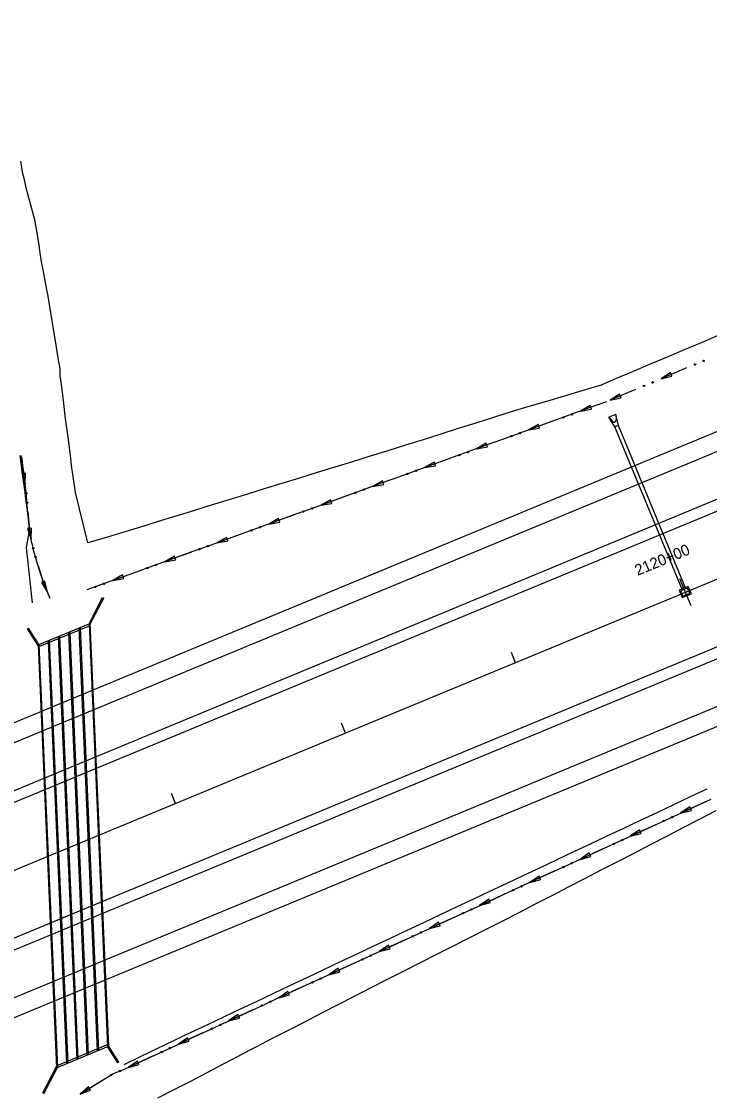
# Model space of a CAD drawing. Extents: x 1611108 to 1749517, y 619561 to 797725.
# Drawn here: x 1717725 to 1718099, y 766360 to 766944 of the extents above; entities that cross this region are included whole.
import ezdxf

# ---------------------------------------------------------------- set-up
doc = ezdxf.new("R2010")
doc.units = 0
for name, color, linetype in [('R_Ditch', 7, 'Continuous'), ('R_Drainage', 7, 'Continuous'), ('R_Horz Alg', 7, 'Continuous'), ('R_Horz Alg Stationing', 7, 'Continuous'), ('R_Proposed Const Limits', 7, 'Continuous'), ('R_Proposed Road', 7, 'Continuous')]:
    doc.layers.add(name, color=color, linetype=linetype)

msp = doc.modelspace()

# ---------------------------------------------------------------- linework, layer by layer
at = {"layer": 'R_Ditch'}
for p, q in [((1718077.71, 766752.79), (1718072.59, 766749.49)), ((1718078.53, 766750.84), (1718077.71, 766752.79)), ((1718072.59, 766749.49), (1718078.53, 766750.84)), ((1718050.03, 766741.13), (1718044.91, 766737.83)), ((1718050.85, 766739.18), (1718050.03, 766741.13)), ((1718034.1, 766734.92), (1718028.82, 766731.88)), ((1718034.82, 766732.93), (1718034.1, 766734.92)), ((1718044.91, 766737.83), (1718050.85, 766739.18)), ((1718028.82, 766731.88), (1718034.82, 766732.93)), ((1718005.86, 766724.69), (1718000.58, 766721.65)), ((1718006.58, 766722.7), (1718005.86, 766724.69)), ((1718000.58, 766721.65), (1718006.58, 766722.7)), ((1717977.62, 766714.45), (1717972.34, 766711.41)), ((1717972.34, 766711.41), (1717978.34, 766712.46)), ((1717978.34, 766712.46), (1717977.62, 766714.45)), ((1717949.38, 766704.22), (1717944.1, 766701.18)), ((1717944.1, 766701.18), (1717950.1, 766702.23)), ((1717950.1, 766702.23), (1717949.38, 766704.22)), ((1717727.26, 766698.18), (1717725.16, 766697.92)), ((1717725.16, 766697.92), (1717726.97, 766692.1)), ((1717726.97, 766692.1), (1717727.26, 766698.18)), ((1717921.14, 766693.99), (1717915.86, 766690.95)), ((1717921.86, 766692), (1717921.14, 766693.99)), ((1717915.86, 766690.95), (1717921.86, 766692)), ((1717892.9, 766683.75), (1717887.62, 766680.71)), ((1717893.62, 766681.76), (1717892.9, 766683.75)), ((1717887.62, 766680.71), (1717893.62, 766681.76)), ((1717864.66, 766673.52), (1717859.38, 766670.48)), ((1717859.38, 766670.48), (1717865.38, 766671.53)), ((1717865.38, 766671.53), (1717864.66, 766673.52)), ((1717730.44, 766668.35), (1717728.35, 766668.02)), ((1717728.35, 766668.02), (1717730.31, 766662.26)), ((1717730.31, 766662.26), (1717730.44, 766668.35)), ((1717836.41, 766663.29), (1717831.13, 766660.25)), ((1717831.13, 766660.25), (1717837.14, 766661.3)), ((1717837.14, 766661.3), (1717836.41, 766663.29)), ((1717808.17, 766653.05), (1717802.89, 766650.02)), ((1717808.89, 766651.06), (1717808.17, 766653.05)), ((1717802.89, 766650.02), (1717808.89, 766651.06)), ((1717779.93, 766642.84), (1717774.64, 766639.8)), ((1717780.65, 766640.85), (1717779.93, 766642.84)), ((1717737.8, 766639.53), (1717735.84, 766638.73)), ((1717735.84, 766638.73), (1717739.1, 766633.58)), ((1717739.1, 766633.58), (1717737.8, 766639.53)), ((1717774.64, 766639.8), (1717780.65, 766640.85)), ((1718088.2, 766516.84), (1718083.19, 766513.37)), ((1718083.19, 766513.37), (1718089.08, 766514.91)), ((1718089.08, 766514.91), (1718088.2, 766516.84)), ((1718060.9, 766504.3), (1718055.89, 766500.84)), ((1718055.89, 766500.84), (1718061.79, 766502.38)), ((1718061.79, 766502.38), (1718060.9, 766504.3)), ((1718033.61, 766491.77), (1718028.59, 766488.3)), ((1718028.59, 766488.3), (1718034.49, 766489.84)), ((1718034.49, 766489.84), (1718033.61, 766491.77)), ((1718006.31, 766479.23), (1718001.3, 766475.77)), ((1718007.19, 766477.31), (1718006.31, 766479.23)), ((1718001.3, 766475.77), (1718007.19, 766477.31)), ((1717979.01, 766466.7), (1717974, 766463.23)), ((1717979.89, 766464.77), (1717979.01, 766466.7)), ((1717974, 766463.23), (1717979.89, 766464.77)), ((1717951.71, 766454.16), (1717946.7, 766450.7)), ((1717946.7, 766450.7), (1717952.6, 766452.24)), ((1717952.6, 766452.24), (1717951.71, 766454.16)), ((1717924.42, 766441.63), (1717919.41, 766438.16)), ((1717919.41, 766438.16), (1717925.3, 766439.7)), ((1717925.3, 766439.7), (1717924.42, 766441.63)), ((1717897.12, 766429.09), (1717892.11, 766425.63)), ((1717892.11, 766425.63), (1717898, 766427.17)), ((1717898, 766427.17), (1717897.12, 766429.09)), ((1717869.83, 766416.54), (1717864.82, 766413.07)), ((1717864.82, 766413.07), (1717870.71, 766414.62)), ((1717870.71, 766414.62), (1717869.83, 766416.54)), ((1717842.55, 766403.96), (1717837.55, 766400.48)), ((1717837.55, 766400.48), (1717843.44, 766402.04)), ((1717843.44, 766402.04), (1717842.55, 766403.96)), ((1717815.29, 766391.34), (1717810.29, 766387.86)), ((1717816.18, 766389.42), (1717815.29, 766391.34)), ((1717810.29, 766387.86), (1717816.18, 766389.42)), ((1717788.04, 766378.7), (1717783.04, 766375.22)), ((1717788.93, 766376.78), (1717788.04, 766378.7)), ((1717783.04, 766375.22), (1717788.93, 766376.78)), ((1717761.39, 766364.75), (1717756.84, 766360.7)), ((1717756.84, 766360.7), (1717762.5, 766362.95)), ((1717762.5, 766362.95), (1717761.39, 766364.75))]:
    msp.add_line(p, q, dxfattribs=at)
for points in [[(1718086.41, 766755.31), (1718079.79, 766752.52), (1718072.59, 766749.49)], [(1718086.45, 766755.33), (1718086.42, 766755.31)], [(1718058.73, 766743.65), (1718052.14, 766740.87), (1718044.91, 766737.83)], [(1718058.77, 766743.66), (1718058.73, 766743.65)], [(1718042.93, 766736.99), (1718033.51, 766733.58), (1718024.1, 766730.17), (1718014.69, 766726.76), (1718005.28, 766723.35), (1717995.87, 766719.94), (1717986.46, 766716.53), (1717977.04, 766713.12), (1717967.63, 766709.71), (1717958.22, 766706.3), (1717948.81, 766702.89), (1717939.4, 766699.48), (1717929.99, 766696.07), (1717920.58, 766692.66), (1717911.17, 766689.25), (1717901.75, 766685.84), (1717892.34, 766682.43), (1717882.93, 766679.02), (1717873.52, 766675.61), (1717864.11, 766672.2), (1717854.7, 766668.79), (1717845.29, 766665.38), (1717835.87, 766661.97), (1717826.46, 766658.56), (1717817.05, 766655.15), (1717807.64, 766651.74), (1717798.23, 766648.33), (1717788.81, 766644.92), (1717779.4, 766641.52), (1717769.98, 766638.12), (1717760.57, 766634.73)], [(1718042.93, 766736.99), (1718033.51, 766733.58), (1718028.82, 766731.88)], [(1718031.09, 766732), (1718031.05, 766731.99)], [(1718014.68, 766726.76), (1718005.28, 766723.35), (1718000.58, 766721.65)], [(1718014.72, 766726.77), (1718014.69, 766726.76), (1718014.68, 766726.76)], [(1717986.44, 766716.52), (1717977.04, 766713.12), (1717972.34, 766711.41)], [(1717986.48, 766716.54), (1717986.46, 766716.53), (1717986.44, 766716.52)], [(1717731, 766627.74), (1717729.94, 766637.74), (1717728.84, 766647.74), (1717727.89, 766656.02), (1717727.69, 766657.75), (1717729.57, 766667.74), (1717728.32, 766677.74), (1717727.26, 766685.85), (1717727.01, 766687.75), (1717725.66, 766697.75), (1717724.26, 766707.75)], [(1717740.55, 766630.04), (1717737.02, 766638.64), (1717733.77, 766648.9), (1717731.47, 766657.1), (1717731.14, 766658.59), (1717730.54, 766660.81), (1717729.46, 766667.75), (1717728.28, 766678.68), (1717727.52, 766687.75), (1717726.25, 766697.75), (1717725.85, 766700.85), (1717724.94, 766707.75)], [(1717725.04, 766706.97), (1717725.85, 766700.85), (1717726.25, 766697.75), (1717726.97, 766692.1)], [(1717958.2, 766706.29), (1717948.81, 766702.89), (1717944.1, 766701.18)], [(1717958.24, 766706.3), (1717958.22, 766706.3), (1717958.2, 766706.29)], [(1717929.96, 766696.06), (1717920.58, 766692.66), (1717915.86, 766690.95)], [(1717930, 766696.07), (1717929.99, 766696.07), (1717929.96, 766696.06)], [(1717901.72, 766685.82), (1717892.34, 766682.43), (1717887.62, 766680.71)], [(1717901.75, 766685.84), (1717901.75, 766685.84), (1717901.72, 766685.82)], [(1717728.45, 766677.17), (1717728.45, 766677.14)], [(1717728.45, 766677.14), (1717729.46, 766667.75), (1717730.31, 766662.26)], [(1717873.48, 766675.59), (1717864.11, 766672.2), (1717859.38, 766670.48)], [(1717873.51, 766675.6), (1717873.48, 766675.59)], [(1717845.24, 766665.36), (1717835.87, 766661.97), (1717831.13, 766660.25)], [(1717845.27, 766665.37), (1717845.24, 766665.36)], [(1717817, 766655.13), (1717807.64, 766651.74), (1717802.89, 766650.02)], [(1717817.03, 766655.14), (1717817, 766655.13)], [(1717734.13, 766647.76), (1717734.14, 766647.73)], [(1717734.14, 766647.73), (1717737.02, 766638.64), (1717739.1, 766633.58)], [(1717788.75, 766644.9), (1717779.4, 766641.52), (1717774.64, 766639.8)], [(1717788.79, 766644.91), (1717788.75, 766644.9)], [(1717780.77, 766376.91), (1717789.8, 766381.22), (1717798.84, 766385.53), (1717807.88, 766389.84), (1717816.93, 766394.14), (1717825.97, 766398.44), (1717835.01, 766402.73), (1717844.06, 766407.03), (1717853.11, 766411.31), (1717862.16, 766415.6), (1717871.21, 766419.88), (1717880.26, 766424.16), (1717889.31, 766428.44), (1717898.36, 766432.71), (1717907.42, 766436.98), (1717916.48, 766441.25), (1717925.53, 766445.52), (1717934.58, 766449.79), (1717943.64, 766454.06), (1717952.7, 766458.33), (1717961.75, 766462.6), (1717970.81, 766466.87), (1717979.86, 766471.14), (1717988.92, 766475.41), (1717997.97, 766479.68), (1718007.03, 766483.95), (1718016.08, 766488.22), (1718025.14, 766492.49), (1718034.19, 766496.76), (1718043.25, 766501.03), (1718052.3, 766505.3), (1718061.36, 766509.57), (1718070.41, 766513.84), (1718079.47, 766518.11), (1718088.52, 766522.38), (1718097.58, 766526.65)], [(1717757.19, 766360.91), (1717774.74, 766371.75), (1717781.72, 766374.6), (1717790.8, 766378.82), (1717799.88, 766383.03), (1717808.96, 766387.24), (1717818.04, 766391.45), (1717827.12, 766395.66), (1717835.73, 766399.64), (1717836.2, 766399.86), (1717845.29, 766404.06), (1717854.38, 766408.25), (1717863.46, 766412.44), (1717872.55, 766416.63), (1717881.64, 766420.81), (1717890.74, 766424.99), (1717899.83, 766429.17), (1717908.92, 766433.35), (1717918.02, 766437.52), (1717927.11, 766441.7), (1717936.21, 766445.88), (1717945.3, 766450.05), (1717954.39, 766454.23), (1717963.49, 766458.41), (1717972.58, 766462.58), (1717981.68, 766466.76), (1717990.77, 766470.93), (1717999.86, 766475.11), (1718008.96, 766479.29), (1718018.05, 766483.46), (1718027.15, 766487.64), (1718036.24, 766491.81), (1718045.33, 766495.99), (1718054.43, 766500.17), (1718063.52, 766504.34), (1718072.62, 766508.52), (1718081.71, 766512.69), (1718090.81, 766516.87), (1718099.9, 766521.05)], [(1718096.82, 766519.63), (1718090.81, 766516.87), (1718083.19, 766513.37)], [(1718096.86, 766519.65), (1718096.82, 766519.63)], [(1718069.52, 766507.1), (1718063.52, 766504.34), (1718055.89, 766500.84)], [(1718069.56, 766507.11), (1718069.52, 766507.1)], [(1718042.23, 766494.56), (1718036.24, 766491.81), (1718028.59, 766488.3)], [(1718042.26, 766494.58), (1718042.23, 766494.56)], [(1718014.93, 766482.03), (1718008.96, 766479.29), (1718001.3, 766475.77)], [(1718014.96, 766482.04), (1718014.93, 766482.03)], [(1717987.63, 766469.49), (1717981.68, 766466.76), (1717974, 766463.23)], [(1717987.67, 766469.51), (1717987.63, 766469.49)], [(1717960.33, 766456.96), (1717954.39, 766454.23), (1717946.7, 766450.7)], [(1717960.37, 766456.97), (1717960.33, 766456.96)], [(1717933.04, 766444.42), (1717927.11, 766441.7), (1717919.41, 766438.16)], [(1717933.07, 766444.44), (1717933.04, 766444.42)], [(1717905.74, 766431.89), (1717899.83, 766429.17), (1717892.11, 766425.63)], [(1717905.77, 766431.9), (1717905.74, 766431.89)], [(1717878.45, 766419.34), (1717872.55, 766416.63), (1717864.82, 766413.07)], [(1717878.48, 766419.36), (1717878.45, 766419.34)], [(1717851.17, 766406.77), (1717845.29, 766404.06), (1717837.55, 766400.48)], [(1717851.2, 766406.78), (1717851.17, 766406.77)], [(1717823.9, 766394.17), (1717818.04, 766391.45), (1717810.29, 766387.86)], [(1717823.93, 766394.18), (1717823.9, 766394.17)], [(1717796.65, 766381.53), (1717790.8, 766378.82), (1717783.04, 766375.22)], [(1717796.68, 766381.55), (1717796.65, 766381.53)], [(1717769.6, 766368.57), (1717757.19, 766360.91)], [(1717769.63, 766368.59), (1717769.6, 766368.57)]]:
    msp.add_lwpolyline(points, dxfattribs=at)
for centre in [(1718095.67, 766759.17), (1718091.06, 766757.23), (1718067.99, 766747.51), (1718063.38, 766745.57), (1718024.13, 766730.14), (1718019.42, 766728.43), (1717991.18, 766718.2), (1717995.89, 766719.91), (1717962.94, 766707.97), (1717967.65, 766709.67), (1717939.4, 766699.44), (1717934.69, 766697.73), (1717911.16, 766689.21), (1717727.61, 766687.13), (1717728.03, 766682.14), (1717906.45, 766687.5), (1717878.21, 766677.27), (1717882.92, 766678.98), (1717849.97, 766667.03), (1717854.68, 766668.74), (1717826.44, 766658.51), (1717731.44, 766657.38), (1717821.73, 766656.8), (1717732.78, 766652.56), (1717798.2, 766648.28), (1717793.49, 766646.57), (1717765.23, 766636.37), (1717769.95, 766638.07), (1718074.1, 766509.16), (1718078.66, 766511.25), (1718046.81, 766496.62), (1718051.36, 766498.72), (1718019.51, 766484.09), (1718024.06, 766486.18), (1717996.76, 766473.65), (1717992.21, 766471.55), (1717969.47, 766461.11), (1717964.91, 766459.02), (1717942.17, 766448.58), (1717937.62, 766446.48), (1717910.32, 766433.95), (1717914.87, 766436.04), (1717883.02, 766421.41), (1717887.57, 766423.5), (1717855.74, 766408.84), (1717860.29, 766410.94), (1717828.47, 766396.24), (1717833.02, 766398.35), (1717805.76, 766385.72), (1717801.22, 766383.62), (1717778.45, 766373.22), (1717773.89, 766371.18)]:
    msp.add_circle(centre, 0.375, dxfattribs=at)
at = {"layer": 'R_Drainage'}
for p, q in [((1718047.96, 766730.06), (1718044.26, 766728.53)), ((1718049.38, 766724.02), (1718047.96, 766730.06)), ((1718047.96, 766730.06), (1718048.21, 766727.13)), ((1718047.53, 766723.26), (1718044.26, 766728.53)), ((1718044.26, 766728.53), (1718046.16, 766726.28)), ((1718049.38, 766724.02), (1718047.53, 766723.26)), ((1718084.27, 766634.56), (1718047.53, 766723.26)), ((1718086.12, 766635.33), (1718049.38, 766724.02)), ((1717761.75, 766616.32), (1717769.14, 766630.51)), ((1717762.27, 766615.87), (1717769.73, 766630.2)), ((1717769.14, 766630.51), (1717769.73, 766630.2)), ((1717728.35, 766613.55), (1717728.91, 766613.91)), ((1717734.07, 766604.56), (1717728.35, 766613.55)), ((1717734.55, 766605.05), (1717728.91, 766613.91)), ((1717734.06, 766604.85), (1717762.25, 766616.52)), ((1717734.11, 766603.79), (1717762.29, 766615.46)), ((1717756.18, 766614.01), (1717766.21, 766384.23)), ((1717756.84, 766614.28), (1717766.87, 766384.5)), ((1717761.75, 766616.32), (1717771.79, 766386.54)), ((1717762.25, 766616.52), (1717772.28, 766386.74)), ((1717739.47, 766607.09), (1717749.5, 766377.31)), ((1717740.12, 766607.36), (1717750.16, 766377.58)), ((1717745.04, 766609.4), (1717755.07, 766379.62)), ((1717745.7, 766609.67), (1717755.73, 766379.89)), ((1717750.61, 766611.7), (1717760.64, 766381.92)), ((1717751.27, 766611.98), (1717761.3, 766382.19)), ((1717734.06, 766604.85), (1717744.09, 766375.07)), ((1717734.55, 766605.05), (1717744.59, 766375.27)), ((1717744.05, 766376.13), (1717772.23, 766387.81)), ((1717744.09, 766375.07), (1717772.28, 766386.74)), ((1717777.43, 766377.68), (1717771.79, 766386.54)), ((1717777.99, 766378.04), (1717772.27, 766387.03)), ((1717736.61, 766361.39), (1717744.07, 766375.72)), ((1717737.2, 766361.08), (1717744.59, 766375.27)), ((1717777.99, 766378.04), (1717777.43, 766377.68)), ((1717737.2, 766361.08), (1717736.61, 766361.39))]:
    msp.add_line(p, q, dxfattribs=at)
for points in [[(1718082.47, 766634.54), (1718084.13, 766630.54), (1718089.06, 766632.58), (1718087.4, 766636.58)], [(1718083.34, 766634.18), (1718084.49, 766631.41), (1718088.19, 766632.94), (1718087.04, 766635.71)]]:
    msp.add_lwpolyline(points, close=True, dxfattribs=at)
msp.add_arc((1718047.05, 766727.03), 1.17, 220.02993, 4.97008, dxfattribs=at)
at = {"layer": 'R_Horz Alg'}
msp.add_line((1715964.86, 765755.05), (1723860.62, 769025.58), dxfattribs=at)
at = {"layer": 'R_Horz Alg Stationing'}
for points in [[(1718082.7, 766640.95), (1718088.83, 766626.17)], [(1717991.08, 766600.84), (1717993.38, 766595.29)], [(1717898.69, 766562.57), (1717900.99, 766557.02)], [(1717806.31, 766524.3), (1717808.6, 766518.76)]]:
    msp.add_lwpolyline(points, dxfattribs=at)
at = {"layer": 'R_Proposed Const Limits'}
for points in [[(1717761.17, 766660.26), (1717754.31, 766687.68), (1717752.89, 766697.69), (1717752.47, 766700.79), (1717751.62, 766707.69), (1717750.33, 766717.69), (1717749.03, 766727.7), (1717747.82, 766737.7), (1717746.54, 766747.7), (1717746.09, 766750.8), (1717746.01, 766754.64), (1717745.8, 766755.99), (1717745.53, 766757.7), (1717744.5, 766764.18), (1717743.93, 766767.71), (1717742.28, 766777.71), (1717740.63, 766787.72), (1717739.28, 766795.49), (1717738.86, 766797.72), (1717736.95, 766807.72), (1717735.98, 766813.04), (1717735.8, 766814.2), (1717735.25, 766817.73), (1717734.76, 766820.83), (1717733.66, 766827.73), (1717732.27, 766835.82), (1717731.74, 766837.74), (1717728.96, 766847.74), (1717727.45, 766853.88), (1717726.59, 766857.75), (1717725.84, 766860.79), (1717724.6, 766867.75)], [(1718039.24, 766745.88), (1718048.45, 766749.77), (1718057.66, 766753.67), (1718066.88, 766757.54), (1718076.11, 766761.41), (1718085.33, 766765.28), (1718094.54, 766769.17), (1718103.74, 766773.08)], [(1718039.24, 766745.88), (1718029.62, 766742.98), (1718020, 766740.08), (1718010.37, 766737.19), (1718000.74, 766734.31), (1717991.12, 766731.41), (1717981.54, 766728.39), (1717971.97, 766725.36), (1717962.4, 766722.34), (1717952.83, 766719.32), (1717943.26, 766716.3), (1717933.67, 766713.31), (1717924.09, 766710.32), (1717914.5, 766707.32), (1717904.91, 766704.34), (1717895.31, 766701.41), (1717885.71, 766698.45), (1717876.11, 766695.49), (1717866.51, 766692.53), (1717856.91, 766689.58), (1717847.31, 766686.62), (1717837.71, 766683.67), (1717828.11, 766680.71), (1717818.51, 766677.75), (1717808.91, 766674.8), (1717799.31, 766671.84), (1717789.72, 766668.88), (1717780.12, 766665.92), (1717770.49, 766663.04), (1717761.17, 766660.26)], [(1717799.14, 766358.67), (1717808.08, 766363.22), (1717816.99, 766367.85), (1717825.88, 766372.52), (1717834.77, 766377.19), (1717843.2, 766381.61), (1717843.66, 766381.86), (1717852.56, 766386.5), (1717861.48, 766391.1), (1717870.43, 766395.62), (1717879.33, 766400.26), (1717888.24, 766404.89), (1717897.16, 766409.48), (1717906.09, 766414.05), (1717915.03, 766418.6), (1717923.97, 766423.15), (1717932.91, 766427.7), (1717941.85, 766432.25), (1717950.79, 766436.8), (1717959.73, 766441.34), (1717968.68, 766445.88), (1717977.62, 766450.42), (1717986.56, 766454.95), (1717995.51, 766459.49), (1718004.44, 766464.06), (1718013.35, 766468.68), (1718022.26, 766473.3), (1718031.17, 766477.92), (1718040.08, 766482.54), (1718049.03, 766487.07), (1718057.96, 766491.65), (1718066.86, 766496.29), (1718075.76, 766500.93), (1718084.66, 766505.57), (1718093.57, 766510.19), (1718102.49, 766514.8)]]:
    msp.add_lwpolyline(points, dxfattribs=at)
at = {"layer": 'R_Proposed Road'}
for p, q in [((1715936.54, 765823.42), (1723832.3, 769093.95)), ((1715940.37, 765814.18), (1723836.12, 769084.71)), ((1715949.55, 765792.01), (1723845.31, 769062.54)), ((1715951.85, 765786.47), (1723847.6, 769056.99)), ((1715977.87, 765723.64), (1723873.63, 768994.17)), ((1715980.17, 765718.1), (1723875.92, 768988.63)), ((1715989.35, 765695.93), (1723885.11, 768966.45)), ((1715993.18, 765686.69), (1723888.93, 768957.22))]:
    msp.add_line(p, q, dxfattribs=at)

# ---------------------------------------------------------------- texts
at = {"layer": 'R_Horz Alg Stationing'}
msp.add_text('2120+00', height=6, rotation=22.5, dxfattribs=at).set_placement((1718059.8, 766642.29))

doc.saveas('drawing.dxf')
